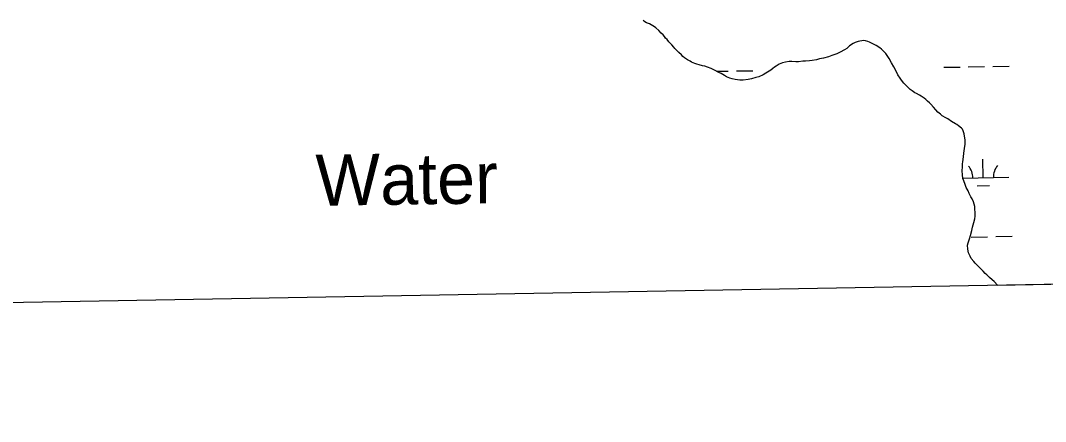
# Model space of a CAD drawing. Extents: x 3903937 to 3942190, y 260677 to 286651.
# Drawn here: x 3921409 to 3923415, y 266016 to 266800 of the extents above; entities that cross this region are included whole.
import ezdxf

# ---------------------------------------------------------------- set-up
doc = ezdxf.new("R2010")
doc.units = 0
for name, color, linetype in [('V-GRID-FRAM', 7, 'Continuous'), ('V-RIVR-IDEN', 7, 'Continuous'), ('V-WETL-SWMP', 7, 'Continuous')]:
    doc.layers.add(name, color=color, linetype=linetype)

msp = doc.modelspace()

# ---------------------------------------------------------------- linework, layer by layer
at = {"layer": 'V-GRID-FRAM'}
msp.add_lwpolyline([(3907892.2, 284196.1), (3939773.2, 284757.2), (3940101.1, 266577.6), (3908204.3, 266016.2), (3907892.2, 284196.1)], dxfattribs=at)
at = {"layer": 'V-WETL-SWMP'}
for p, q in [((3922631.1, 266797.5), (3922627.5, 266800.1)), ((3922634.5, 266795.8), (3922631.1, 266797.5)), ((3922639.9, 266793.4), (3922634.5, 266795.8)), ((3922643.1, 266791.4), (3922639.9, 266793.4)), ((3922649.8, 266787.6), (3922643.1, 266791.4)), ((3922652.7, 266785.7), (3922649.8, 266787.6)), ((3922658.2, 266780.6), (3922652.7, 266785.7)), ((3922663.2, 266775.4), (3922658.2, 266780.6)), ((3922666.6, 266771.8), (3922663.2, 266775.4)), ((3922669.3, 266768.9), (3922666.6, 266771.8)), ((3922671.7, 266765.7), (3922669.3, 266768.9)), ((3922674.4, 266762.8), (3922671.7, 266765.7)), ((3922678.2, 266758.4), (3922674.4, 266762.8)), ((3923048.6, 266759.2), (3923042.9, 266757.3)), ((3923051.7, 266759.8), (3923048.6, 266759.2)), ((3923056, 266760.4), (3923051.7, 266759.8)), ((3923059.5, 266760.7), (3923056, 266760.4)), ((3923063, 266760.2), (3923059.5, 266760.7)), ((3923067.2, 266759), (3923063, 266760.2)), ((3923070.7, 266757.9), (3923067.2, 266759)), ((3922680.5, 266755.9), (3922678.2, 266758.4)), ((3922684, 266752.3), (3922680.5, 266755.9)), ((3922687.4, 266748.3), (3922684, 266752.3)), ((3922689.7, 266745.4), (3922687.4, 266748.3)), ((3922694.2, 266741.1), (3922689.7, 266745.4)), ((3922697.6, 266737.8), (3922694.2, 266741.1)), ((3923021.7, 266742.8), (3923013.5, 266738.1)), ((3923026.3, 266745.5), (3923021.7, 266742.8)), ((3923031.8, 266750.6), (3923026.3, 266745.5)), ((3923038.6, 266755.3), (3923031.8, 266750.6)), ((3923042.9, 266757.3), (3923038.6, 266755.3)), ((3923078.3, 266754.1), (3923070.7, 266757.9)), ((3923083.5, 266751.5), (3923078.3, 266754.1)), ((3923090.8, 266747), (3923083.5, 266751.5)), ((3923094.5, 266744.1), (3923090.8, 266747)), ((3923099.3, 266739.1), (3923094.5, 266744.1)), ((3923102.4, 266735.8), (3923099.3, 266739.1)), ((3922702.4, 266732.7), (3922697.6, 266737.8)), ((3922705.4, 266729.8), (3922702.4, 266732.7)), ((3922708.9, 266727.3), (3922705.4, 266729.8)), ((3922714.7, 266723.2), (3922708.9, 266727.3)), ((3922719.6, 266720.3), (3922714.7, 266723.2)), ((3922722.3, 266718.8), (3922719.6, 266720.3)), ((3922913.4, 266719.7), (3922906.3, 266718.5)), ((3922918.6, 266719.9), (3922913.4, 266719.7)), ((3922926.4, 266719.6), (3922918.6, 266719.9)), ((3922931.6, 266719.5), (3922926.4, 266719.6)), ((3922940.1, 266720.3), (3922931.6, 266719.5)), ((3922945.4, 266720.5), (3922940.1, 266720.3)), ((3922953.2, 266721.3), (3922945.4, 266720.5)), ((3922958.4, 266721.8), (3922953.2, 266721.3)), ((3922966.9, 266723.3), (3922958.4, 266721.8)), ((3922973, 266724.9), (3922966.9, 266723.3)), ((3922980.4, 266726.5), (3922973, 266724.9)), ((3922990.7, 266729.3), (3922980.4, 266726.5)), ((3922997.1, 266731.6), (3922990.7, 266729.3)), ((3923007, 266735.2), (3922997.1, 266731.6)), ((3923013.5, 266738.1), (3923007, 266735.2)), ((3923106.4, 266730), (3923102.4, 266735.8)), ((3923109.5, 266725.7), (3923106.4, 266730)), ((3923114.1, 266717.5), (3923109.5, 266725.7)), ((3922728.6, 266716.1), (3922722.3, 266718.8)), ((3922732.8, 266714.9), (3922728.6, 266716.1)), ((3922737.3, 266713.4), (3922732.8, 266714.9)), ((3922743.9, 266711.4), (3922737.3, 266713.4)), ((3922748.5, 266710.6), (3922743.9, 266711.4)), ((3922753.3, 266708.7), (3922748.5, 266710.6)), ((3922760.6, 266706), (3922753.3, 266708.7)), ((3922768.3, 266702.3), (3922760.6, 266706)), ((3922775.9, 266698.5), (3922768.3, 266702.3)), ((3922771.3, 266700.8), (3922794.2, 266701.2)), ((3922810.2, 266701.4), (3922842.2, 266702)), ((3922874.1, 266701.2), (3922867.7, 266697.2)), ((3922877.3, 266703.2), (3922874.1, 266701.2)), ((3922881.3, 266706.2), (3922877.3, 266703.2)), ((3922884.9, 266708.9), (3922881.3, 266706.2)), ((3922887.8, 266710.6), (3922884.9, 266708.9)), ((3922894.2, 266714.6), (3922887.8, 266710.6)), ((3922897.1, 266716), (3922894.2, 266714.6)), ((3922900.3, 266717.3), (3922897.1, 266716)), ((3922906.3, 266718.5), (3922900.3, 266717.3)), ((3923118.5, 266709.3), (3923114.1, 266717.5)), ((3923121.5, 266703.6), (3923118.5, 266709.3)), ((3923126.4, 266693.9), (3923121.5, 266703.6)), ((3923216, 266708.6), (3923248, 266709.2)), ((3923264, 266709.4), (3923296, 266710)), ((3923312, 266710.3), (3923344, 266710.8)), ((3922780.1, 266696.6), (3922775.9, 266698.5)), ((3922786.6, 266692.9), (3922780.1, 266696.6)), ((3922790.8, 266690.3), (3922786.6, 266692.9)), ((3922797, 266687.7), (3922790.8, 266690.3)), ((3922802.2, 266686.1), (3922797, 266687.7)), ((3922807.8, 266684.9), (3922802.2, 266686.1)), ((3922816.9, 266683.6), (3922807.8, 266684.9)), ((3922823.3, 266683.7), (3922816.9, 266683.6)), ((3922833.2, 266684.8), (3922823.3, 266683.7)), ((3922839.9, 266686.4), (3922833.2, 266684.8)), ((3922848.4, 266688.6), (3922839.9, 266686.4)), ((3922854.1, 266690.2), (3922848.4, 266688.6)), ((3922862.3, 266694.1), (3922854.1, 266690.2)), ((3922867.7, 266697.2), (3922862.3, 266694.1)), ((3923130.5, 266687.5), (3923126.4, 266693.9)), ((3923133.2, 266683.5), (3923130.5, 266687.5)), ((3923137.9, 266677.7), (3923133.2, 266683.5)), ((3923143, 266672.3), (3923137.9, 266677.7)), ((3923146.1, 266669.4), (3923143, 266672.3)), ((3923150.5, 266665.4), (3923146.1, 266669.4)), ((3923154.3, 266662.5), (3923150.5, 266665.4)), ((3923159.5, 266658.8), (3923154.3, 266662.5)), ((3923163, 266657.3), (3923159.5, 266658.8)), ((3923168.5, 266654.3), (3923163, 266657.3)), ((3923172, 266652.1), (3923168.5, 266654.3)), ((3923177.8, 266648), (3923172, 266652.1)), ((3923180.9, 266645.5), (3923177.8, 266648)), ((3923184.3, 266642.6), (3923180.9, 266645.5)), ((3923188.4, 266638.9), (3923184.3, 266642.6)), ((3923190.8, 266636.4), (3923188.4, 266638.9)), ((3923195.9, 266630.6), (3923190.8, 266636.4)), ((3923200.7, 266625.5), (3923195.9, 266630.6)), ((3923204.8, 266621.2), (3923200.7, 266625.5)), ((3923209.6, 266616.8), (3923204.8, 266621.2)), ((3923213, 266613.9), (3923209.6, 266616.8)), ((3923219.9, 266609.8), (3923213, 266613.9)), ((3923224.1, 266607.6), (3923219.9, 266609.8)), ((3923231.3, 266602.8), (3923224.1, 266607.6)), ((3923238.9, 266598.4), (3923231.3, 266602.8)), ((3923242, 266596.5), (3923238.9, 266598.4)), ((3923244.8, 266594.3), (3923242, 266596.5)), ((3923250.6, 266589.9), (3923244.8, 266594.3)), ((3923252.7, 266587.4), (3923250.6, 266589.9)), ((3923254, 266584.2), (3923252.7, 266587.4)), ((3923256.3, 266578.5), (3923254, 266584.2)), ((3923256.8, 266574.3), (3923256.3, 266578.5)), ((3923258, 266566.8), (3923256.8, 266574.3)), ((3923258.1, 266558), (3923258, 266566.8)), ((3923254.6, 266533.5), (3923255.1, 266540.9)), ((3923255.1, 266540.9), (3923257.3, 266554.5)), ((3923257.3, 266554.5), (3923258.1, 266558)), ((3923252.6, 266514.2), (3923252.7, 266520.2)), ((3923252.7, 266520.2), (3923253.2, 266523.7)), ((3923253.2, 266523.7), (3923254.6, 266533.5)), ((3923293.3, 266492.7), (3923292.6, 266528.7)), ((3923252.3, 266506.2), (3923252.6, 266514.2)), ((3923252.8, 266498.4), (3923252.3, 266506.2)), ((3923253.6, 266491.3), (3923252.8, 266498.4)), ((3923253.6, 266492), (3923343.2, 266493.6)), ((3923255.2, 266486.4), (3923253.6, 266491.3)), ((3923257.8, 266479.3), (3923255.2, 266486.4)), ((3923259.8, 266473.9), (3923257.8, 266479.3)), ((3923263.8, 266466.8), (3923259.8, 266473.9)), ((3923266.1, 266462.1), (3923263.8, 266466.8)), ((3923269.4, 266455.7), (3923266.1, 266462.1)), ((3923281.5, 266477), (3923305.5, 266477.5)), ((3923271.4, 266451.4), (3923269.4, 266455.7)), ((3923274.4, 266445.3), (3923271.4, 266451.4)), ((3923275.3, 266441.1), (3923274.4, 266445.3)), ((3923276.6, 266436.8), (3923275.3, 266441.1)), ((3923277.1, 266430.5), (3923276.6, 266436.8)), ((3923277.7, 266425.2), (3923277.1, 266430.5)), ((3923277.4, 266417.8), (3923277.7, 266425.2)), ((3923272.6, 266395.8), (3923274.9, 266404.9)), ((3923274.9, 266404.9), (3923276.6, 266412.6)), ((3923276.6, 266412.6), (3923277.4, 266417.8)), ((3923266.3, 266373.5), (3923268.2, 266379.8)), ((3923268.2, 266379.8), (3923271, 266389.5)), ((3923271, 266389.5), (3923272.6, 266395.8)), ((3923317.9, 266377.7), (3923349.9, 266378.2)), ((3923262.7, 266360.6), (3923263.6, 266365.5)), ((3923263.2, 266352.8), (3923262.7, 266360.6)), ((3923263.6, 266365.5), (3923266.3, 266373.5)), ((3923269.9, 266376.8), (3923301.9, 266377.4)), ((3923264.4, 266345.8), (3923263.2, 266352.8)), ((3923267.7, 266339.7), (3923264.4, 266345.8)), ((3923270, 266335), (3923267.7, 266339.7)), ((3923274.8, 266328.9), (3923270, 266335)), ((3923277.5, 266326), (3923274.8, 266328.9)), ((3923281.9, 266321.3), (3923277.5, 266326)), ((3923285.3, 266318), (3923281.9, 266321.3)), ((3923289.8, 266313.3), (3923285.3, 266318)), ((3923293.2, 266310.1), (3923289.8, 266313.3)), ((3923297.3, 266305.7), (3923293.2, 266310.1)), ((3923300.4, 266302.8), (3923297.3, 266305.7)), ((3923305.5, 266297.7), (3923300.4, 266302.8)), ((3923311, 266293), (3923305.5, 266297.7)), ((3923314.7, 266289.7), (3923311, 266293)), ((3923321.2, 266282.8), (3923314.7, 266289.7)), ((3923321.6, 266282.3), (3923321.2, 266282.8)), ((3923735.9, 266289.6), (3923321.6, 266282.3))]:
    msp.add_line(p, q, dxfattribs=at)
for centre, start, end in [((3923238, 266492.2), 0.2366, 41.7802), ((3923348.5, 266494.1), 140.2366, 181.7802)]:
    msp.add_arc(centre, 35.2, start, end, dxfattribs=at)

# ---------------------------------------------------------------- texts
at = {"layer": 'V-RIVR-IDEN'}
msp.add_text('Water', height=100, rotation=0.8107, dxfattribs=at).set_placement((3921987.2, 266437.8))

doc.saveas('drawing.dxf')
